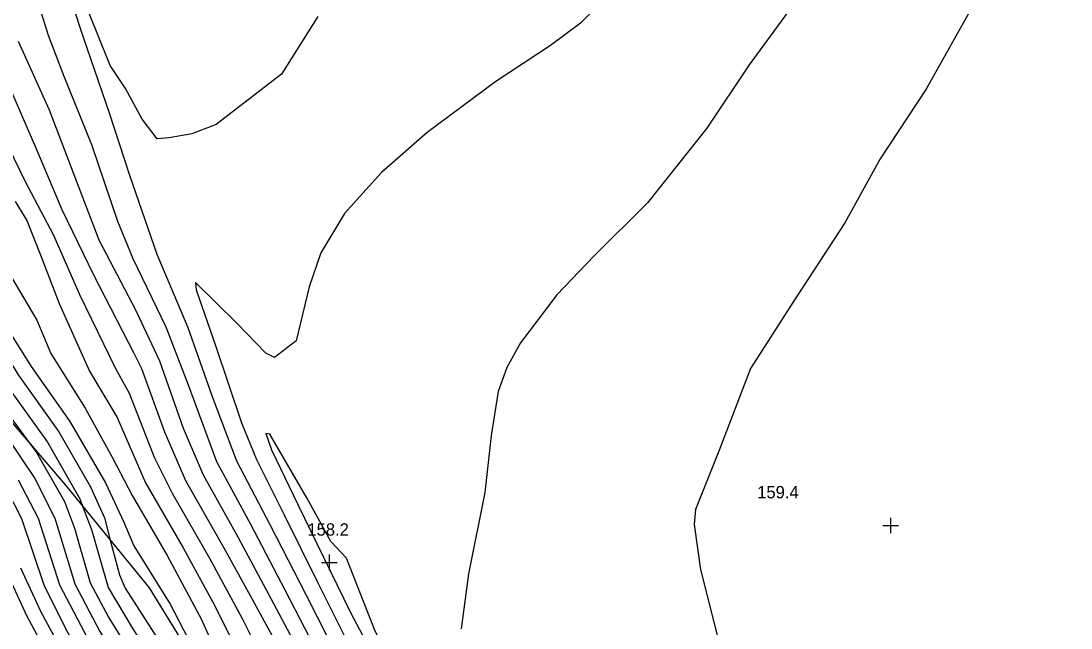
# Model space of a CAD drawing. Extents: x 1475150 to 2003689, y 770235 to 1112803.
# Drawn here: x 2002659.6 to 2002829.1, y 771183.5 to 771281.4 of the extents above; entities that cross this region are included whole.
import ezdxf

# ---------------------------------------------------------------- set-up
doc = ezdxf.new("R2010")
doc.units = 0
for name, color, linetype in [('RD_DTM_Major1', 7, 'Continuous'), ('RD_DTM_Major2', 7, 'Continuous'), ('RD_DTM_Minor1', 7, 'Continuous'), ('RD_DTM_Minor2', 7, 'Continuous'), ('RD_DTM_Obscure', 7, 'Continuous'), ('RD_DTM_Spot_Elev', 7, 'Continuous')]:
    doc.layers.add(name, color=color, linetype=linetype)

msp = doc.modelspace()

# ---------------------------------------------------------------- linework, layer by layer
at = {"layer": 'RD_DTM_Major1'}
for points in [[(2002660.45, 771290.53), (2002664.03, 771279.15), (2002666.55, 771272.51), (2002671.03, 771261.51), (2002675.22, 771249.11), (2002677.66, 771243.1), (2002683.03, 771232.06), (2002686.59, 771222.7), (2002691.2, 771210.33), (2002696.69, 771200.21), (2002702.21, 771189.63), (2002708.59, 771177.35)], [(2002657.82, 771240.5), (2002662.21, 771233.14), (2002664.47, 771227.79), (2002669.98, 771218.95), (2002674.34, 771211.03), (2002677.55, 771204.84), (2002683.25, 771195.19), (2002688.78, 771184.84), (2002691.37, 771179.02)]]:
    msp.add_lwpolyline(points, dxfattribs=at)
at = {"layer": 'RD_DTM_Major2'}
msp.add_lwpolyline([(2002654.53, 771218.04), (2002657.25, 771214.47), (2002661.88, 771207.57), (2002665.07, 771201.19), (2002668.33, 771190.58), (2002672.37, 771182.9), (2002679.57, 771170.99), (2002683.76, 771163.78), (2002685.58, 771159.2), (2002690.3, 771152.5), (2002695.01, 771145.03), (2002698.68, 771139.17), (2002704.48, 771129.17), (2002711.31, 771116.67), (2002715.88, 771105.6), (2002718.71, 771098.65), (2002724.7, 771088.03), (2002731.15, 771076.17), (2002737.25, 771064.57), (2002741.23, 771052.36), (2002742.65, 771048.71), (2002746.13, 771042.89), (2002752.29, 771034.5), (2002755.03, 771032.17)], dxfattribs=at)
at = {"layer": 'RD_DTM_Minor1'}
for points in [[(2002575.89, 771351.44), (2002576.58, 771350.03), (2002582.73, 771342.53), (2002589.49, 771333.59), (2002595.87, 771323.12), (2002600.5, 771316.2), (2002609.15, 771305.7), (2002610.34, 771301.7), (2002611.17, 771297.43), (2002612.62, 771293.24), (2002615, 771288.4), (2002618.08, 771283.68), (2002626.3, 771273.43), (2002633.38, 771263.74), (2002637.32, 771257.61), (2002638.82, 771253.7), (2002641.43, 771244.88), (2002643.81, 771241.14), (2002651.57, 771232.08), (2002657.87, 771221.85), (2002663.92, 771213.45), (2002669.14, 771204.3), (2002669.57, 771203.14)], [(2002573.94, 771349.72), (2002574.3, 771348.98), (2002576.95, 771345.69), (2002584.23, 771337.11), (2002589.63, 771329.59), (2002596.09, 771318.77), (2002601.43, 771310.98), (2002606.98, 771303.89), (2002607.87, 771300.41), (2002609.33, 771295.5), (2002613.46, 771286.7), (2002616.75, 771281.28), (2002623.47, 771272.76), (2002628.82, 771265.82), (2002635.27, 771256.35), (2002636.53, 771253.08), (2002638.81, 771245.8), (2002641.47, 771240.88), (2002644.82, 771236.58), (2002648.99, 771231.6), (2002655.05, 771221.37), (2002661.06, 771213.22)], [(2002759.77, 771291.08), (2002749.92, 771281.08), (2002745.1, 771277.45), (2002736.27, 771271.65), (2002725.2, 771263.41), (2002717.81, 771256.95), (2002711.82, 771250.33), (2002708.05, 771244.01), (2002706.12, 771238.53), (2002704.05, 771229.81), (2002700.53, 771227.12), (2002699.16, 771227.82), (2002694.47, 771232.66), (2002687.8, 771239.22), (2002687.91, 771238.05), (2002691.05, 771229.06), (2002695.24, 771216.56), (2002697.63, 771210.68), (2002702.09, 771201.72), (2002707.56, 771190.77), (2002712.23, 771181.42)], [(2002666.14, 771289.61), (2002669.72, 771278.66), (2002673.85, 771266.59), (2002677.17, 771256.52), (2002681.54, 771243.82), (2002686.56, 771231.98), (2002690.51, 771220.83), (2002694.42, 771210.47), (2002699.8, 771200.16), (2002705.6, 771188.85), (2002711.11, 771178.04)], [(2002813.97, 771285.15), (2002805.78, 771270.5), (2002798.32, 771259.18), (2002792.61, 771248.85), (2002784.19, 771235.97), (2002777.35, 771225.35), (2002772.26, 771212.03), (2002768.49, 771202.57), (2002768.28, 771200.15), (2002769.28, 771192.91), (2002772.52, 771180.14), (2002774.47, 771174.75), (2002775.24, 771174.34), (2002781.28, 771172.81), (2002795.1, 771169.47), (2002801.77, 771167.82), (2002811.44, 771166.48), (2002820.52, 771165.55), (2002823.48, 771164.73), (2002826.87, 771163.2), (2002829.11, 771161.75)], [(2002620.4, 771284.79), (2002627.7, 771275.75), (2002634.98, 771265.73), (2002639.37, 771258.87), (2002641.12, 771254.32), (2002644.06, 771244.25), (2002647.11, 771241.07), (2002651.72, 771236.05), (2002655.09, 771230.98), (2002659.16, 771224.32), (2002665.72, 771215.11), (2002670.85, 771206.26), (2002673.09, 771201.25), (2002674.04, 771197.67)], [(2002784.67, 771284.62), (2002777.17, 771274.33), (2002770.32, 771264.1), (2002760.74, 771252.06), (2002752.17, 771243.51), (2002746.14, 771237.24), (2002740.23, 771229.48), (2002738.03, 771225.49), (2002736.65, 771221.63), (2002735.54, 771214.52), (2002734.52, 771205.31), (2002731.85, 771192.22), (2002730.65, 771183.33)], [(2002626.23, 771282.02), (2002632.93, 771272.81), (2002640.12, 771262.5), (2002642.5, 771257.82), (2002643.96, 771252.97), (2002645.8, 771246.23), (2002649.11, 771242.59), (2002654, 771237.12), (2002657.83, 771231.18), (2002661.26, 771225.68), (2002667.52, 771216.78), (2002673.25, 771206.89), (2002676.25, 771200.55), (2002677.87, 771196.72), (2002683.73, 771187.33), (2002686.54, 771181.81), (2002688.22, 771177.12)], [(2002707.56, 771282.14), (2002701.69, 771272.86), (2002691.11, 771264.7), (2002687.18, 771263.19), (2002683.56, 771262.59), (2002681.59, 771262.4), (2002679.19, 771265.56), (2002677.53, 771268.62), (2002676.51, 771270.55), (2002674.05, 771274.25), (2002671.72, 771280), (2002670.62, 771282.62)], [(2002659.19, 771278.16), (2002664.19, 771267.1), (2002668.14, 771256.66), (2002672.2, 771246.12), (2002678.12, 771234.83), (2002681.97, 771226.56), (2002685.82, 771215.71), (2002689.03, 771208.19), (2002694.67, 771198.06), (2002699.97, 771188.21), (2002706.5, 771175.89)], [(2002658.14, 771269.86), (2002662.13, 771260.66), (2002666.23, 771251.01), (2002671.35, 771240.47), (2002677.86, 771227.81), (2002679.09, 771225.32), (2002682.8, 771215.1), (2002686.2, 771207.28), (2002692.35, 771196.4), (2002696.92, 771188.12), (2002703.67, 771175.79)], [(2002655.78, 771264.73), (2002660.23, 771255.65), (2002664.86, 771246.84), (2002669.07, 771237.3), (2002674.9, 771225.37), (2002677.11, 771221.37), (2002681.1, 771211.02), (2002684.07, 771205.14), (2002690.03, 771194.72), (2002695.34, 771185), (2002700.45, 771174.81)], [(2002658.67, 771252.3), (2002660.56, 771249.21), (2002662.82, 771243.55), (2002665.81, 771235.82), (2002670.68, 771224.89), (2002675.13, 771217.42), (2002679.74, 771206.9), (2002685.81, 771196.38), (2002690.9, 771187.05), (2002695.92, 771176.94)], [(2002707.37, 771197.09), (2002712.79, 771185.98), (2002718.98, 771174.28), (2002720.73, 771171.89), (2002720.88, 771172.3), (2002719.47, 771177.63), (2002718.15, 771180.33), (2002716.79, 771182.95), (2002712.15, 771194.75), (2002710.51, 771196.54), (2002709.63, 771197.45), (2002705.79, 771204.45), (2002699.81, 771214.74), (2002699.16, 771214.85), (2002700.08, 771212.21), (2002704.38, 771203.29), (2002707.37, 771197.09)]]:
    msp.add_lwpolyline(points, dxfattribs=at)
at = {"layer": 'RD_DTM_Minor2'}
for points in [[(2002644.94, 771213.79), (2002646.68, 771211.07), (2002654.38, 771201.11), (2002656.87, 771193.46), (2002660.57, 771185.39), (2002666.94, 771173.58), (2002675.07, 771159.41), (2002681.48, 771147.8), (2002685.24, 771141.72), (2002690.25, 771133.09), (2002697.53, 771120.49), (2002705.83, 771105.64), (2002710.2, 771095.31), (2002714.36, 771087.8), (2002719.59, 771077.94), (2002727.4, 771063.25), (2002729.65, 771058.92), (2002733.04, 771047.46), (2002734.7, 771044.17), (2002738.92, 771038.02), (2002745.57, 771029.85), (2002751.93, 771023.76), (2002752.19, 771023.44)], [(2002661.06, 771213.22), (2002662.12, 771211.79), (2002666.63, 771203.87), (2002668.26, 771199.58), (2002670.82, 771190.74), (2002673.73, 771185.23), (2002680.4, 771174.4)], [(2002659.2, 771207.38), (2002662.4, 771201.17), (2002665.84, 771190.43), (2002671.01, 771180.57), (2002678.75, 771167.59), (2002682.38, 771161.16), (2002684.08, 771157.36), (2002687.21, 771152.96), (2002693.45, 771142.93), (2002697.86, 771135.45), (2002704.95, 771123.15), (2002710.57, 771112.42), (2002714.59, 771102.42), (2002717.55, 771095.94), (2002724.01, 771084.52), (2002730.85, 771071.8), (2002734.98, 771064.15), (2002736.81, 771057.75), (2002739.42, 771048.99), (2002741.4, 771045.52), (2002748.74, 771035.59), (2002751.45, 771032.54), (2002754.79, 771029.55)], [(2002657.25, 771205.96), (2002659.72, 771201.15), (2002663.35, 771190.27), (2002667.13, 771182.8), (2002674.59, 771169.69), (2002681.25, 771157.72), (2002682.15, 771156.09), (2002685.02, 771151.88), (2002689.4, 771144.62), (2002692.96, 771138.73), (2002698.14, 771129.8), (2002705.38, 771117.18), (2002709.31, 771109.39), (2002713.25, 771099.56), (2002716.3, 771093.6), (2002721.61, 771084.08), (2002727.91, 771072.25), (2002733.24, 771062.24), (2002735.83, 771052.55), (2002737.14, 771047.83), (2002740.32, 771043.27), (2002748.82, 771032.32), (2002754.1, 771027.52)], [(2002669.57, 771203.14), (2002671.01, 771199.36), (2002673.72, 771190.03), (2002677.57, 771183.52), (2002684.56, 771172.53), (2002687.01, 771167.53), (2002689.27, 771161.95), (2002695.57, 771153.12), (2002701.55, 771144.09), (2002706.68, 771135.74), (2002712.64, 771125.02), (2002716.41, 771116.65), (2002719.82, 771108.23), (2002723.31, 771099.64), (2002728.3, 771090.75), (2002734.4, 771080.1), (2002740.66, 771068.85), (2002743.84, 771060.98), (2002745.38, 771057.67), (2002749.2, 771047.69), (2002752.28, 771043.5), (2002755.7, 771039.38)], [(2002674.04, 771197.67), (2002675.52, 771192.07), (2002676.45, 771189.89), (2002682.05, 771181.21), (2002688.04, 771171.17), (2002691.12, 771163.32), (2002697.57, 771154.43), (2002703.92, 771144.92), (2002709.69, 771135.69), (2002713.78, 771127.98)], [(2002659.56, 771193.17), (2002662.76, 771186.16), (2002668.3, 771175.91), (2002675.78, 771162.97), (2002679.74, 771155.55), (2002685.03, 771146.7), (2002688.28, 771141.61), (2002692.79, 771133.88), (2002699.27, 771122.66), (2002707.3, 771108.15), (2002711.08, 771098.77), (2002713.73, 771093.6), (2002719.22, 771083.64), (2002726.28, 771070.29), (2002731.95, 771058.99), (2002735.46, 771046.82), (2002738.8, 771041.78), (2002747.2, 771031.08), (2002752.5, 771026.11), (2002753.13, 771025.46)]]:
    msp.add_lwpolyline(points, dxfattribs=at)
at = {"layer": 'RD_DTM_Obscure'}
msp.add_lwpolyline([(2002656.63, 771218.38), (2002666.82, 771206.52), (2002680.34, 771189.94), (2002698.53, 771160.36), (2002716.96, 771121.22), (2002732.3, 771089.9), (2002750.02, 771051.59), (2002755.78, 771040.25), (2002754.72, 771028.85), (2002749.61, 771017.94), (2002730.31, 771026.46)], dxfattribs=at)
at = {"layer": 'RD_DTM_Spot_Elev'}
for p, q in [((2002800, 771198.75), (2002800, 771201.25)), ((2002798.75, 771200), (2002801.25, 771200)), ((2002709.4, 771192.81), (2002709.4, 771195.31)), ((2002708.15, 771194.06), (2002710.65, 771194.06))]:
    msp.add_line(p, q, dxfattribs=at)

# ---------------------------------------------------------------- texts
for s, p in [('159.4', (2002778.46, 771204.39)), ('158.2', (2002705.86, 771198.37))]:
    msp.add_text(s, height=2, dxfattribs=at).set_placement(p)

doc.saveas('drawing.dxf')
